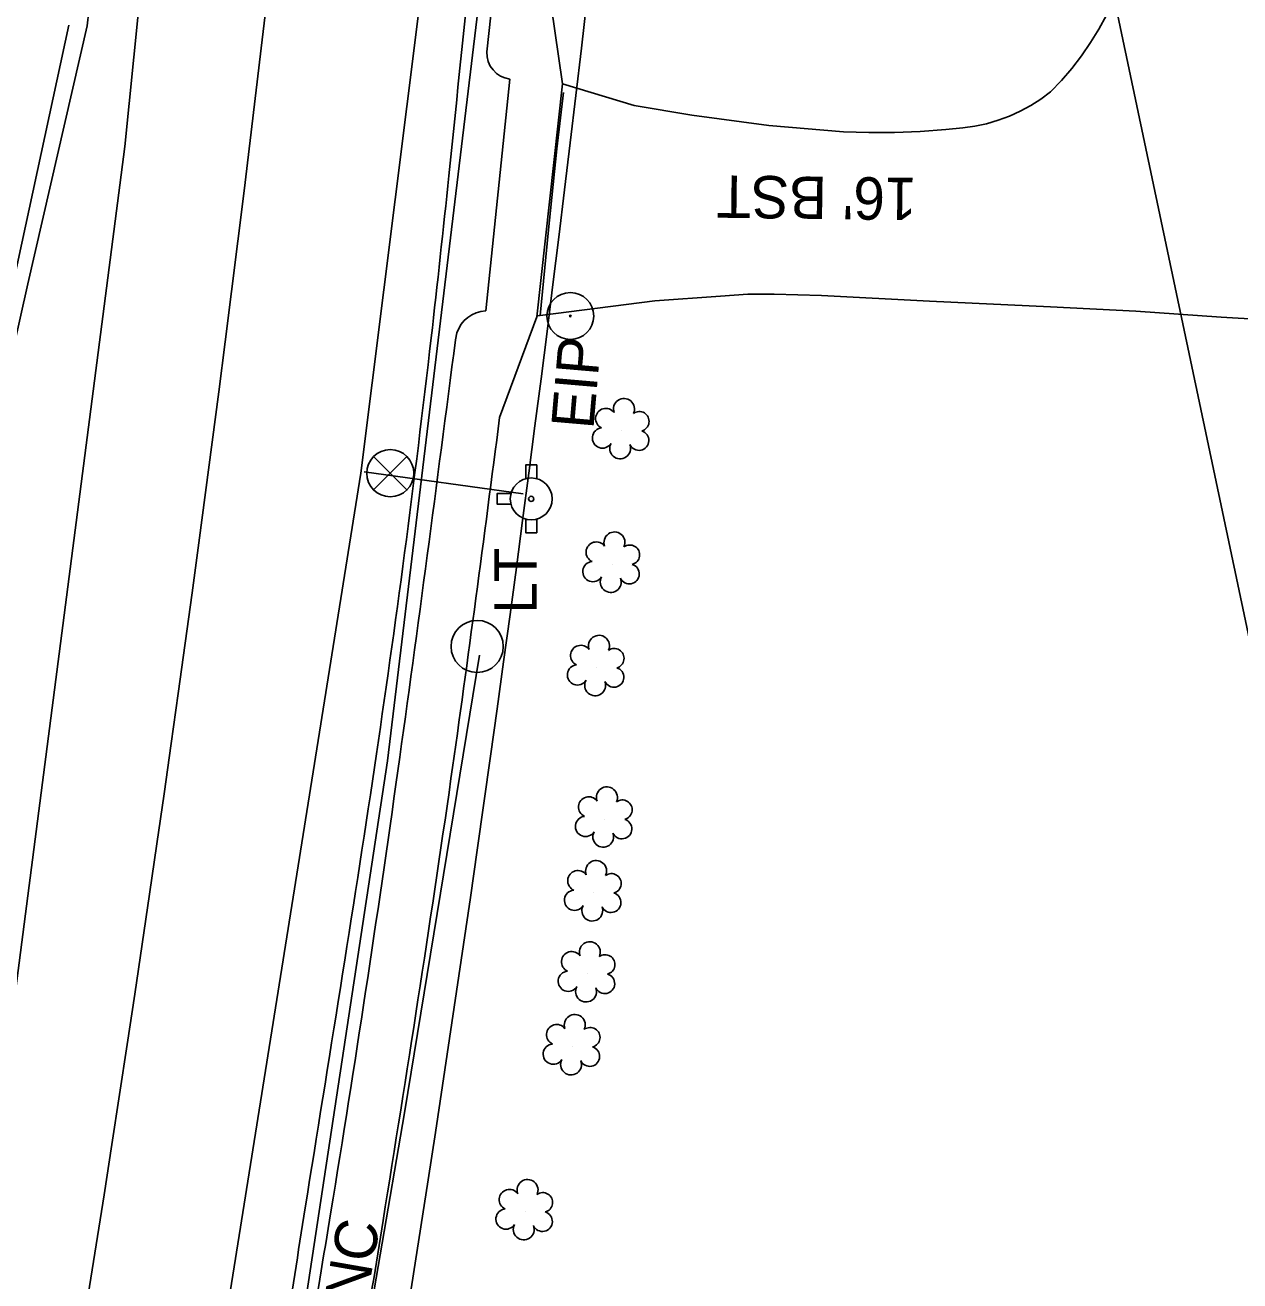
# Model space of a CAD drawing. Extents: x 1614611 to 1617571, y 898867 to 905462.
# Drawn here: x 1616651.2 to 1616765.8, y 901813.1 to 901931.6 of the extents above; entities that cross this region are included whole.
import ezdxf

# ---------------------------------------------------------------- set-up
doc = ezdxf.new("R2010")
doc.units = 0
for name, color, linetype in [('Exist Boundary Watershed Impervious C 09', 7, 'Continuous'), ('Exist Boundary Watershed Residential C 05', 7, 'Continuous'), ('Exist Drainage Structure Drop Inlet CELL', 7, 'Continuous'), ('Exist Plan Preparation Watershed Yellow', 7, 'Continuous'), ('Exist Roads Change in Surface', 7, 'Continuous'), ('Exist Roads Curbs Text', 7, 'Continuous'), ('Exist Roads EOT Text', 7, 'Continuous'), ('Exist Utilities Other Pole CELL', 7, 'Continuous'), ('Exist Utilities Other Pole Text', 7, 'Continuous'), ('Exist Utilities Telephone UG Cable SUE LOS B', 7, 'Continuous'), ('Exist Utilities Telephone UG FO SUE LOS B', 7, 'Continuous'), ('Exist Utilities Water UG Line SUE LOS B', 7, 'Continuous'), ('Exist Vegetation Shrub CELL', 7, 'Continuous'), ('Prop Drainage Structure Catch Basin Grate 840 03E Label', 7, 'Continuous'), ('Prop Earthen Structure Base Ditch Detail CELL', 7, 'Continuous'), ('Prop Earthen Structure Head Ditch Label', 7, 'Continuous'), ('Prop Earthen Structure V Ditch Detail Label', 7, 'Continuous'), ('Raster_Level_2', 7, 'Continuous'), ('Scratch_Level_1', 7, 'Continuous'), ('Scratch_Level_9', 7, 'Continuous')]:
    doc.layers.add(name, color=color, linetype=linetype)

# ---------------------------------------------------------------- blocks, each defined once
blk = doc.blocks.new('EXIST PROPERTY IRON PIN')
at = {"layer": 'Exist Plan Preparation Watershed Yellow'}
for radius in [0.0441, 0.00141]:
    blk.add_circle((0, 0), radius, dxfattribs=at)
blk = doc.blocks.new('EXIST UTILITIES WATER FIRE HYDRANT')
at = {"layer": 'Prop Earthen Structure Base Ditch Detail CELL'}
blk.add_line((0, 0), (0, 0), dxfattribs=at)
for points in [[(-0.01025, 0.03825), (-0.01025, 0.064), (0.01025, 0.064), (0.01025, 0.03775)], [(-0.03825, 0.01025), (-0.064, 0.01025), (-0.064, -0.01025), (-0.03825, -0.01025)], [(-0.01025, -0.03825), (-0.01025, -0.064), (0.01025, -0.064), (0.01025, -0.03775)]]:
    blk.add_lwpolyline(points, dxfattribs=at)
for radius in [0.03954, 0.00485]:
    blk.add_circle((0, 0), radius, dxfattribs=at)
blk = doc.blocks.new('EXIST UTILITIES WATER VALVE')
at = {"layer": 'Prop Earthen Structure V Ditch Detail Label'}
blk.add_lwpolyline([(0.0315, 0.0315), (-0.0315, -0.0315), (0, 0), (0.0315, -0.0315), (-0.0315, 0.0315)], dxfattribs=at)
blk.add_circle((0, 0), 0.0445, dxfattribs=at)

msp = doc.modelspace()

# ---------------------------------------------------------------- linework, layer by layer
at = {"layer": 'Exist Boundary Watershed Impervious C 09'}
msp.add_lwpolyline([(1616623.04, 901776.71), (1616628.63, 901802.84), (1616634.16, 901828.59), (1616642.69, 901868.2), (1616651.43, 901907.18), (1616657.03, 901931.53)], dxfattribs=at)
msp.add_spline([(1616657.03, 901931.53), (1616661.72, 901975.47), (1616665.32, 902018.62), (1616668.31, 902062.36), (1616670.59, 902105.52), (1616672.4, 902149.47), (1616673.48, 902193.66), (1616673.75, 902239.27), (1616673.47, 902282.77), (1616672.23, 902328.42), (1616670.01, 902372.56), (1616668.01, 902402.36), (1616665.45, 902433.28)], degree=3, dxfattribs=at)
at = {"layer": 'Exist Boundary Watershed Residential C 05'}
for p, q in [((1616695.5, 901936.25), (1616694.74, 901929.08)), ((1616696.9, 901926.51), (1616694.64, 901904.65)), ((1616691.9, 901902.56), (1616691.77, 901901.9))]:
    msp.add_line(p, q, dxfattribs=at)
for centre, major_axis, ratio, start_param, end_param in [((1616697.17, 901928.93), (1.58, -1.87), 0.989475, 3.954405, 5.466267), ((1616694.79, 901901.61), (-2.66, -1.49), 0.998654, 4.251308, 5.453682)]:
    msp.add_ellipse(centre, major_axis=major_axis, ratio=ratio, start_param=start_param, end_param=end_param, dxfattribs=at)
msp.add_spline([(1616691.77, 901901.9), (1616686.34, 901861.26), (1616680.02, 901819.66), (1616675.75, 901794.24), (1616671.27, 901768.31), (1616666.01, 901740.71), (1616660.97, 901714.53)], degree=3, dxfattribs=at)
at = {"layer": 'Exist Roads Change in Surface'}
msp.add_lwpolyline([(1616699.75, 901904.21), (1616700.52, 901911.96), (1616701.35, 901919.93), (1616701.95, 901925.23)], dxfattribs=at)
at = {"layer": 'Exist Utilities Other Pole CELL'}
msp.add_circle((1616693.82, 901872.99), 2.46, dxfattribs=at)
at = {"layer": 'Exist Utilities Telephone UG Cable SUE LOS B'}
msp.add_lwpolyline([(1616586.65, 901614.7), (1616592.7, 901627.45), (1616597.67, 901647), (1616601.16, 901647.82), (1616608.45, 901646.9), (1616613.6, 901651.99), (1616633.98, 901750.98), (1616649.47, 901834.39), (1616660.58, 901920.16), (1616668.64, 902000.09), (1616671.96, 902044.94), (1616671.51, 902046.39), (1616670.53, 902047.17), (1616656.18, 902049.88), (1616655.65, 902049.04), (1616655.13, 902049.4), (1616655.43, 902048.87), (1616655.12, 902049.21)], dxfattribs=at)
at = {"layer": 'Exist Utilities Telephone UG FO SUE LOS B'}
msp.add_lwpolyline([(1616583, 901316.53), (1616602.93, 901389.19), (1616611.41, 901436.2), (1616627.53, 901512.28), (1616643.11, 901593.04), (1616647.49, 901611.03), (1616645.52, 901612.27), (1616650.47, 901635.14), (1616653.42, 901650.24), (1616659.31, 901688.22), (1616659.33, 901688.62), (1616660.8, 901715.96), (1616675.12, 901794.59), (1616685.37, 901862.2), (1616699.64, 901980.75), (1616706.3, 902030.47), (1616708.52, 902097.65)], dxfattribs=at)
at = {"layer": 'Exist Utilities Water UG Line SUE LOS B'}
msp.add_line((1616698.16, 901887.4), (1616683.17, 901889.47), dxfattribs=at)
for points in [[(1616682.85, 901889.35), (1616688.26, 901932.45), (1616696.61, 902016.19), (1616699.26, 902055.42), (1616702.78, 902110.39), (1616705.34, 902181.72), (1616707.31, 902255.35), (1616706.62, 902316.75), (1616703.14, 902377.45), (1616699.12, 902434.84), (1616686.86, 902524.85), (1616669.78, 902622.34), (1616658.13, 902681.62), (1616634.87, 902784.56), (1616617.17, 902853.52), (1616602.15, 902900.61), (1616584.28, 902954.24), (1616571.86, 902993.81)], [(1616569.55, 901320.83), (1616578, 901357.2), (1616604.16, 901478.07), (1616624.61, 901573.86), (1616638.86, 901640.83), (1616644.54, 901672.71), (1616659.76, 901744.73), (1616682.85, 901889.35)]]:
    msp.add_lwpolyline(points, dxfattribs=at)
at = {"layer": 'Exist Vegetation Shrub CELL'}
for p, q in [((1616707.44, 901893.35), (1616707.44, 901893.35)), ((1616706.54, 901880.76), (1616706.54, 901880.76)), ((1616705.08, 901871.01), (1616705.08, 901871.01)), ((1616705.84, 901856.71), (1616705.84, 901856.71)), ((1616704.81, 901849.76), (1616704.81, 901849.76)), ((1616704.22, 901842.11), (1616704.22, 901842.11)), ((1616702.8, 901835.24), (1616702.8, 901835.24)), ((1616698.34, 901819.67), (1616698.34, 901819.67))]:
    msp.add_line(p, q, dxfattribs=at)
for centre, radius, start, end in [((1616707.67, 901895.39), 0.99, 334.8391, 200.4717), ((1616705.96, 901894.48), 0.968, 35.8908, 245.4216), ((1616709.11, 901894.22), 0.929, 284.4567, 126.0861), ((1616705.64, 901892.65), 0.955, 95.1099, 327.9534), ((1616709.08, 901892.42), 0.937, 204.9913, 73.4601), ((1616707.31, 901891.67), 0.984, 151.2797, 21.387), ((1616706.77, 901882.8), 0.99, 334.8391, 200.4717), ((1616705.06, 901881.88), 0.968, 35.8908, 245.4216), ((1616708.22, 901881.63), 0.929, 284.4567, 126.0861), ((1616704.74, 901880.05), 0.955, 95.1099, 327.9534), ((1616708.18, 901879.83), 0.937, 204.9913, 73.4601), ((1616706.42, 901879.07), 0.984, 151.2797, 21.387), ((1616705.31, 901873.05), 0.99, 334.8391, 200.4717), ((1616703.6, 901872.13), 0.968, 35.8908, 245.4216), ((1616706.75, 901871.87), 0.929, 284.4567, 126.0861), ((1616703.28, 901870.3), 0.955, 95.1099, 327.9534), ((1616706.72, 901870.08), 0.937, 204.9913, 73.4601), ((1616704.95, 901869.32), 0.984, 151.2797, 21.387), ((1616706.06, 901858.75), 0.99, 334.8391, 200.4717), ((1616704.35, 901857.84), 0.968, 35.8908, 245.4216), ((1616707.51, 901857.58), 0.929, 284.4567, 126.0861), ((1616704.04, 901856.01), 0.955, 95.1099, 327.9534), ((1616707.47, 901855.78), 0.937, 204.9913, 73.4601), ((1616705.71, 901855.03), 0.984, 151.2797, 21.387), ((1616703.33, 901850.88), 0.968, 35.8908, 245.4216), ((1616705.04, 901851.8), 0.99, 334.8391, 200.4717), ((1616706.48, 901850.63), 0.929, 284.4567, 126.0861), ((1616703.01, 901849.05), 0.955, 95.1099, 327.9534), ((1616706.45, 901848.83), 0.937, 204.9913, 73.4601), ((1616704.68, 901848.07), 0.984, 151.2797, 21.387), ((1616704.45, 901844.15), 0.99, 334.8391, 200.4717), ((1616702.74, 901843.24), 0.968, 35.8908, 245.4216), ((1616705.89, 901842.98), 0.929, 284.4567, 126.0861), ((1616702.42, 901841.4), 0.955, 95.1099, 327.9534), ((1616705.86, 901841.18), 0.937, 204.9913, 73.4601), ((1616704.09, 901840.43), 0.984, 151.2797, 21.387), ((1616703.03, 901837.28), 0.99, 334.8391, 200.4717), ((1616701.32, 901836.36), 0.968, 35.8908, 245.4216), ((1616704.48, 901836.11), 0.929, 284.4567, 126.0861), ((1616701, 901834.53), 0.955, 95.1099, 327.9534), ((1616704.44, 901834.31), 0.937, 204.9913, 73.4601), ((1616702.68, 901833.55), 0.984, 151.2797, 21.387), ((1616698.57, 901821.71), 0.99, 334.8391, 200.4717), ((1616696.86, 901820.8), 0.968, 35.8908, 245.4216), ((1616700.01, 901820.54), 0.929, 284.4567, 126.0861), ((1616696.54, 901818.97), 0.955, 95.1099, 327.9534), ((1616699.98, 901818.74), 0.937, 204.9913, 73.4601), ((1616698.21, 901817.99), 0.984, 151.2797, 21.387)]:
    msp.add_arc(centre, radius, start, end, dxfattribs=at)
at = {"layer": 'Prop Drainage Structure Catch Basin Grate 840 03E Label'}
msp.add_lwpolyline([(1616668.72, 901703.15), (1616667.26, 901711.66), (1616675.49, 901762.01), (1616686.97, 901828.98), (1616694.04, 901872.18)], dxfattribs=at)
at = {"layer": 'Prop Earthen Structure Head Ditch Label'}
msp.add_line((1616010.65, 905462.23), (1616993.32, 900797.76), dxfattribs=at)
msp.add_arc((1613828.3, 902264.36), 2894.79, 348.38093, 354.06667, dxfattribs=at)
at = {"layer": 'Raster_Level_2'}
msp.add_arc((1613828.3, 902264.38), 2864.79, 347.94618, 354.06667, dxfattribs=at)
at = {"layer": 'Scratch_Level_1'}
for points in [[(1616700.45, 901935.86), (1616701.86, 901926.05), (1616699.44, 901904.08), (1616695.94, 901894.59)], [(1616701.86, 901926.05), (1616708.62, 901924.01), (1616714.06, 901923.12), (1616721.33, 901922.14), (1616728.37, 901921.54), (1616730.78, 901921.47), (1616733.2, 901921.48), (1616735.61, 901921.57), (1616738.02, 901921.74), (1616739.65, 901921.9), (1616740.77, 901922.06), (1616741.88, 901922.3), (1616742.96, 901922.62), (1616744.03, 901923.01), (1616745.06, 901923.48), (1616746.06, 901924.02), (1616747.01, 901924.63), (1616747.91, 901925.3), (1616748.95, 901926.38), (1616749.93, 901927.52), (1616750.84, 901928.71), (1616751.69, 901929.95), (1616752.48, 901931.23), (1616753.19, 901932.54)], [(1616777.86, 901903.3), (1616772.1, 901903.58), (1616764.02, 901904.06), (1616755.97, 901904.63), (1616747.92, 901905.02), (1616736.48, 901905.57), (1616726.3, 901906.08), (1616721.84, 901906.23), (1616719.37, 901906.22), (1616716.79, 901906.03), (1616710.59, 901905.6), (1616699.75, 901904.21), (1616699.54, 901904.19)]]:
    msp.add_lwpolyline(points, dxfattribs=at)
msp.add_spline([(1616695.94, 901894.59), (1616691.35, 901860.52), (1616684.94, 901818.83), (1616680.8, 901793.73), (1616676.08, 901767.37), (1616671.02, 901740.02), (1616665.83, 901713.67)], degree=3, dxfattribs=at)
at = {"layer": 'Scratch_Level_9'}
msp.add_lwpolyline([(1616621.64, 901776.98), (1616627.39, 901803.1), (1616632.77, 901828.92), (1616641.71, 901868.37), (1616650.08, 901907.37), (1616655.28, 901931.6)], dxfattribs=at)
msp.add_spline([(1616700.93, 902023.09), (1616697.48, 901980.45), (1616693.1, 901936.47), (1616691.15, 901917.39), (1616689.48, 901902.09), (1616684.13, 901861.58), (1616677.6, 901820.03), (1616673.54, 901794.89), (1616668.88, 901768.87), (1616663.9, 901741.21), (1616658.75, 901714.99)], degree=3, dxfattribs=at)

# ---------------------------------------------------------------- block references
at = {"layer": 'Exist Plan Preparation Watershed Yellow', "xscale": 50, "yscale": 50}
msp.add_blockref('EXIST PROPERTY IRON PIN', (1616702.61, 901904.16), dxfattribs=at)
at = {"layer": 'Prop Earthen Structure Base Ditch Detail CELL', "xscale": 50, "yscale": 50}
msp.add_blockref('EXIST UTILITIES WATER FIRE HYDRANT', (1616698.92, 901886.91), dxfattribs=at)
at = {"layer": 'Prop Earthen Structure V Ditch Detail Label', "xscale": 50, "yscale": 50}
msp.add_blockref('EXIST UTILITIES WATER VALVE', (1616685.62, 901889.33), dxfattribs=at)

# ---------------------------------------------------------------- texts
at = {"layer": 'Exist Drainage Structure Drop Inlet CELL'}
msp.add_text('EIP', height=4, rotation=85.075, dxfattribs=at).set_placement((1616704.78, 901893.41))
at = {"layer": 'Exist Roads Curbs Text'}
msp.add_text('60" CONC', height=4, rotation=80.0912, dxfattribs=at).set_placement((1616680.36, 901793.84))
at = {"layer": 'Exist Roads EOT Text'}
msp.add_text("16' BST", height=4, rotation=179.2569, dxfattribs=at).set_placement((1616735.3, 901917.19))
at = {"layer": 'Exist Utilities Other Pole Text'}
msp.add_text('LT', height=4, rotation=90, dxfattribs=at).set_placement((1616699.43, 901876.07))

doc.saveas('drawing.dxf')
